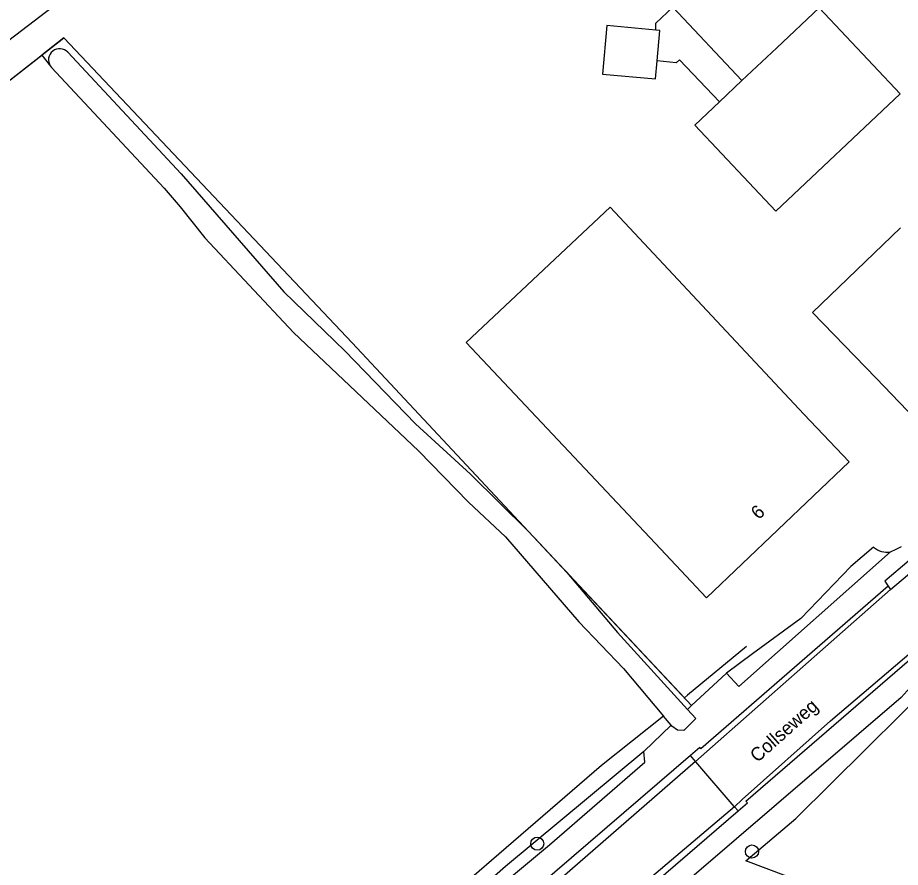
# Model space of a CAD drawing. Extents: x 164494 to 166241, y 382475 to 384494.
# Drawn here: x 165288.9 to 165354.5, y 384025.1 to 384088.3 of the extents above; entities that cross this region are included whole.
import ezdxf

# ---------------------------------------------------------------- set-up
doc = ezdxf.new("R2010")
doc.units = 0
for name, color, linetype in [('IMGEO_Berm_halfverhard', 7, 'Continuous'), ('IMGEO_Berm_open', 7, 'Continuous'), ('IMGEO_Boom', 7, 'Continuous'), ('IMGEO_Grasland_agrarisch', 7, 'Continuous'), ('IMGEO_Grasland_overig', 7, 'Continuous'), ('IMGEO_Groenvoorziening', 7, 'Continuous'), ('IMGEO_Hek', 7, 'Continuous'), ('IMGEO_Openbare_ruimte_label', 7, 'Continuous'), ('IMGEO_Pand', 7, 'Continuous'), ('IMGEO_Pand_nummerreeks', 7, 'Continuous'), ('IMGEO_Rijbaan_lokaal_gesloten', 7, 'Continuous'), ('IMGEO_Waterloop', 7, 'Continuous')]:
    doc.layers.add(name, color=color, linetype=linetype)

msp = doc.modelspace()

# ---------------------------------------------------------------- linework, layer by layer
at = {"layer": 'IMGEO_Berm_halfverhard'}
for points in [[(165342.457, 384029.327), (165343.149, 384029.924), (165343.032, 384030.052), (165361.191, 384045.73), (165378.251, 384059.429)], [(165353.618, 384046.006), (165339.695, 384033.942), (165339.626, 384034.037), (165338.914, 384033.424)], [(165338.914, 384033.424), (165325.135, 384021.562)], [(165339.3, 384032.977), (165338.914, 384033.424)], [(165328.664, 384017.425), (165342.457, 384029.327)], [(165342.457, 384029.327), (165342.196, 384029.629)]]:
    msp.add_lwpolyline(points, dxfattribs=at)
at = {"layer": 'IMGEO_Berm_open'}
for points in [[(165355.158, 384047.926), (165353.349, 384046.386), (165353.618, 384046.006)], [(165353.618, 384046.006), (165353.778, 384045.772)]]:
    msp.add_lwpolyline(points, dxfattribs=at)
at = {"layer": 'IMGEO_Boom'}
for centre in [(165327.543, 384026.884), (165343.493, 384026.298)]:
    msp.add_circle(centre, 0.489, dxfattribs=at)
at = {"layer": 'IMGEO_Grasland_agrarisch'}
for points in [[(165324.577, 384114.294), (165317.6, 384108.966), (165252.153, 384058.979)], [(165253.127, 384057.056), (165268.295, 384067.905), (165290.735, 384085.47)]]:
    msp.add_lwpolyline(points, dxfattribs=at)
at = {"layer": 'IMGEO_Grasland_overig'}
for points in [[(165326.891, 384050.086), (165313.785, 384064.085), (165292.37, 384086.749), (165290.735, 384085.47)], [(165290.735, 384085.47), (165291.38, 384084.656)], [(165336.908, 384036.367), (165332.31, 384032.682), (165315.061, 384017.793), (165296.281, 384001.565), (165284.444, 383991.515), (165283.396, 383990.941), (165282.076, 383990.49), (165280.345, 383990.016), (165276.77, 383990.922), (165272.974, 383992.834), (165263.468, 383999.193), (165260.537, 384001.907), (165257.429, 384007.085), (165256.928, 384011.049), (165258.646, 384020.059)], [(165335.45, 384033.721), (165337.481, 384035.681)]]:
    msp.add_lwpolyline(points, dxfattribs=at)
at = {"layer": 'IMGEO_Groenvoorziening'}
for points in [[(165353.783, 384048.557), (165354.194, 384048.759), (165354.605, 384048.96)], [(165329.75, 384047.033), (165339.009, 384037.144)], [(165339.009, 384037.144), (165341.59, 384039.543)], [(165339.009, 384037.144), (165338.707, 384036.864)]]:
    msp.add_lwpolyline(points, dxfattribs=at)
at = {"layer": 'IMGEO_Hek'}
for points in [[(165253.127, 384057.056), (165268.295, 384067.905), (165292.37, 384086.749), (165313.785, 384064.085), (165326.891, 384050.086)], [(165338.713, 384037.924), (165338.468, 384037.722), (165327.318, 384049.631)], [(165343.084, 384041.54), (165338.713, 384037.924)]]:
    msp.add_lwpolyline(points, dxfattribs=at)
at = {"layer": 'IMGEO_Pand'}
for points in [[(165336.344, 384087.331), (165336.359, 384087.849), (165337.606, 384089.026), (165342.75, 384083.575)], [(165342.75, 384083.575), (165345.33, 384086.01), (165348.485, 384088.987), (165354.508, 384082.604), (165345.259, 384073.877), (165339.236, 384080.26), (165341.068, 384081.988)], [(165336.344, 384087.331), (165332.72, 384087.663), (165332.389, 384084.057), (165336.314, 384083.697), (165336.438, 384085.049)], [(165336.438, 384085.049), (165336.645, 384087.303), (165336.344, 384087.331)], [(165341.068, 384081.988), (165338.113, 384085.12), (165337.868, 384084.889), (165336.438, 384085.049)], [(165341.068, 384081.988), (165342.75, 384083.575)], [(165347.349, 384058.806), (165350.703, 384055.242), (165340.124, 384045.146), (165336.698, 384048.787), (165322.274, 384064.121), (165332.965, 384074.179), (165347.349, 384058.806)], [(165362.702, 384064.146), (165361.201, 384062.699), (165356.175, 384057.856), (165352.706, 384061.457), (165347.988, 384066.354), (165354.518, 384072.645)]]:
    msp.add_lwpolyline(points, dxfattribs=at)
at = {"layer": 'IMGEO_Rijbaan_lokaal_gesloten'}
for points in [[(165342.196, 384029.629), (165342.774, 384030.162), (165349.337, 384036.022), (165357.153, 384042.664), (165368.742, 384052.317), (165379.087, 384060.555), (165384.606, 384064.9), (165389.473, 384068.311), (165394.851, 384071.884), (165398.403, 384074.002)], [(165353.778, 384045.772), (165361.803, 384052.529), (165380.141, 384067.277)], [(165339.3, 384032.977), (165353.778, 384045.772)], [(165339.3, 384032.977), (165325.577, 384021.044)], [(165342.192, 384029.633), (165342.18, 384029.647), (165339.311, 384032.965), (165339.3, 384032.977)], [(165342.192, 384029.633), (165328.3, 384017.851)], [(165342.196, 384029.629), (165342.192, 384029.633)]]:
    msp.add_lwpolyline(points, dxfattribs=at)
at = {"layer": 'IMGEO_Waterloop'}
for points in [[(165292.678, 384085.685), (165301.093, 384076.655), (165308.723, 384067.888), (165313.252, 384063.5), (165318.507, 384058.078), (165322.591, 384054.348), (165326.891, 384050.086)], [(165291.38, 384084.656), (165291.463, 384084.552), (165299.817, 384075.596), (165301.022, 384074.192), (165302.838, 384071.905), (165309.424, 384064.873), (165318.721, 384056.08), (165322.446, 384052.267), (165325.183, 384049.687), (165330.625, 384043.365), (165333.948, 384039.91), (165336.908, 384036.367)], [(165348.876, 384023.417), (165343.024, 384025.615), (165346.76, 384028.762), (165359.803, 384041.672), (165362.707, 384043.753), (165374.751, 384053.736), (165379.062, 384057.607), (165381.07, 384059.101), (165382.106, 384059.628), (165382.283, 384060.069), (165381.762, 384060.186), (165380.109, 384059.294), (165371.241, 384052.452), (165365.795, 384048.014), (165355.922, 384039.225), (165354.573, 384037.755), (165333.093, 384019.286)], [(165326.891, 384050.086), (165329.75, 384047.033)], [(165352.53, 384048.91), (165350.846, 384047.468), (165347.115, 384043.622), (165343.541, 384040.983), (165341.59, 384039.543)], [(165341.59, 384039.543), (165342.506, 384038.557), (165353.783, 384048.557)], [(165329.75, 384047.033), (165333.509, 384042.566), (165338.707, 384036.864)], [(165338.707, 384036.864), (165339.33, 384036.181), (165338.418, 384035.282), (165337.958, 384035.319), (165337.536, 384035.616), (165337.481, 384035.681)], [(165337.481, 384035.681), (165336.908, 384036.367)], [(165282.52, 383986.145), (165283.547, 383986.655), (165284.63, 383987.46), (165285.87, 383988.632), (165292.307, 383994.716), (165294.231, 383996.254), (165306.385, 384007.779), (165318.663, 384018.644), (165328.461, 384026.792), (165335.536, 384032.942), (165335.45, 384033.721)], [(165335.45, 384033.721), (165325.174, 384025.19), (165316.571, 384017.609), (165310.172, 384012.285), (165305.148, 384007.51), (165286.771, 383991.023), (165285.244, 383989.372)]]:
    msp.add_lwpolyline(points, dxfattribs=at)
for centre, radius, start, end in [((165292.07, 384085.118), 0.831, 42.99741, 213.8144), ((165353.536, 384050.08), 1.543, 229.31259, 279.21982)]:
    msp.add_arc(centre, radius, start, end, dxfattribs=at)

# ---------------------------------------------------------------- texts
at = {"layer": 'IMGEO_Openbare_ruimte_label'}
msp.add_text('Collseweg', height=1, rotation=41.75725, dxfattribs=at).set_placement((165343.896, 384032.865))
at = {"layer": 'IMGEO_Pand_nummerreeks'}
msp.add_text('6', height=1, rotation=43.65938, dxfattribs=at).set_placement((165343.991, 384050.91))

doc.saveas('drawing.dxf')
